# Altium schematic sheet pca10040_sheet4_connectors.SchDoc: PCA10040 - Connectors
size A3; Revision: 1.1.0; SheetNumber: 4; SheetTotal: 5; DrawnBy: KJP; ProjectNumber: 4397; PCAName: PCA10040; PCBRevision: 0071KJP; DocumentSize: A3; PCBNumber: 400150
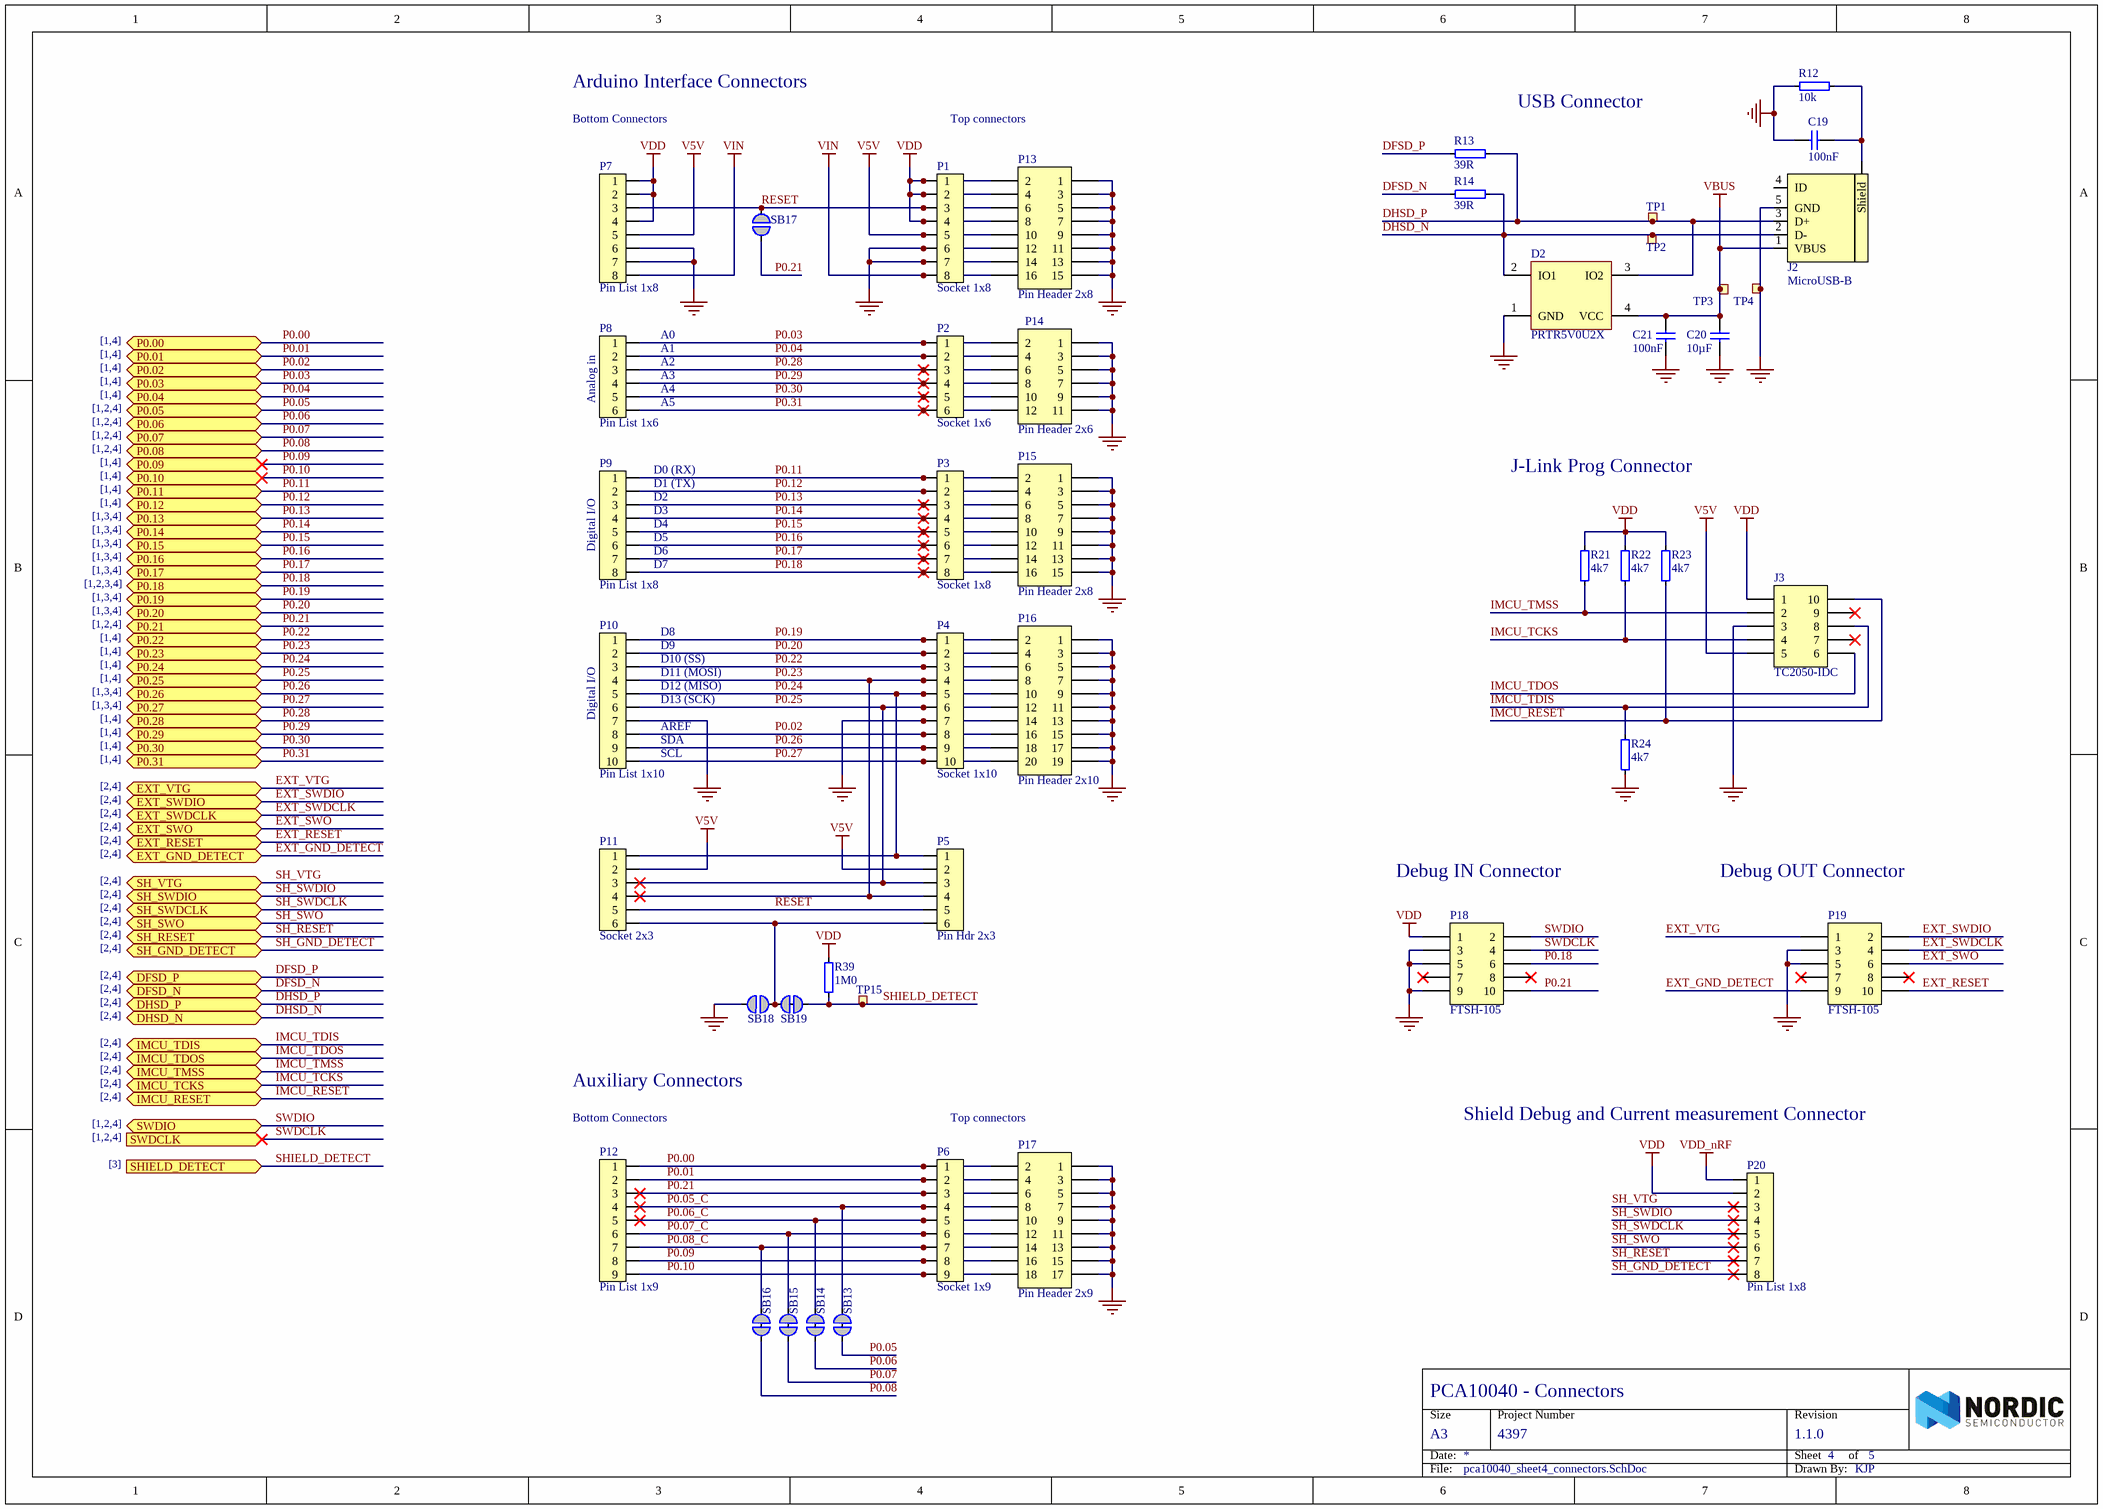
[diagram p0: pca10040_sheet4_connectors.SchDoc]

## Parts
C19  100nF  [CAPC1005X04L]
C20  10µF  [CAPC1608X06L]
C21  100nF  [CAPC1005X04L]
D2  PRTR5V0U2X  [SOT190P230X110-4L]
J2  MicroUSB-B  [FCI_10118193-0001LF]
J3  TC2050-IDC  [TC2050-IDC-NLFP]  (no BOM)
P1  Socket 1x8  [SOCKET_1x8_SMD]
P2  Socket 1x6  [SOCKET_1x6_SMD]
P3  Socket 1x8  [SOCKET_1x8_SMD]
P4  Socket 1x10  [SOCKET_1x10_SMD]
P5  Pin Hdr 2x3  [Molex 15-91-2060]
P6  Socket 1x9  [SOCKET_1x9_SMD]
P7  Pin List 1x8  [LIST_1x8_SMD]
P8  Pin List 1x6  [LIST_1x6_SMD]
P9  Pin List 1x8  [LIST_1x8_SMD]
P10  Pin List 1x10  [LIST_1x10_SMD]
P11  Socket 2x3  [SOCKET_2x3_SMD-2.54mm-bottom]
P12  Pin List 1x9  [LIST_1x9_SMD]
P13  Pin Header 2x8  [HDR_2x8]
P14  Pin Header 2x6  [HDR_2x6]
P15  Pin Header 2x8  [HDR_2x8]
P16  Pin Header 2x10  [HDR_2x10]
P17  Pin Header 2x9  [HDR_2x9]
P18  FTSH-105  [FTSH-105-K]
P19  FTSH-105  [FTSH-105-K]
P20  Pin List 1x8  [LIST_1x8_SMD]
R12  10k  [RESC1005X04L]
R13  39R  [RESC1005X04L]
R14  39R  [RESC1005X04L]
R21  4k7  [RESC1005X04L]
R22  4k7  [RESC1005X04L]
R23  4k7  [RESC1005X04L]
R24  4k7  [RESC1005X04L]
R39  1M0  [RESC1005X04L]
SB13  Solderbridge  [Solderbridge_Shorted]  (value not drawn)  (net tie, no BOM)
SB14  Solderbridge  [Solderbridge_Shorted]  (value not drawn)  (net tie, no BOM)
SB15  Solderbridge  [Solderbridge_Shorted]  (value not drawn)  (net tie, no BOM)
SB16  Solderbridge  [Solderbridge_Shorted]  (value not drawn)  (net tie, no BOM)
SB17  Solderbridge  [Solderbridge]  (value not drawn)  (no BOM)
SB18  Solderbridge  [Solderbridge]  (value not drawn)  (no BOM)
SB19  Solderbridge  [Solderbridge_Shorted]  (value not drawn)  (net tie, no BOM)
TP1  Ø1.0mm,SMD  [TP_SMD_Ø1.0mm]  (value not drawn)  (no BOM)
TP2  Ø1.0mm,SMD  [TP_SMD_Ø1.0mm]  (value not drawn)  (no BOM)
TP3  Ø1.0mm,SMD  [TP_SMD_Ø1.0mm]  (value not drawn)  (no BOM)
TP4  Ø1.0mm,SMD  [TP_SMD_Ø1.0mm]  (value not drawn)  (no BOM)
TP15  Ø1.0mm,SMD  [TP_SMD_Ø1.0mm]  (value not drawn)  (no BOM)

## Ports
DFSD_N (bidir), DFSD_P (bidir), DHSD_N (bidir), DHSD_P (bidir), EXT_GND_DETECT (bidir), EXT_RESET (bidir), EXT_SWDCLK (bidir), EXT_SWDIO (bidir), EXT_SWO (bidir), EXT_VTG (bidir), IMCU_RESET (bidir), IMCU_TCKS (bidir), IMCU_TDIS (bidir), IMCU_TDOS (bidir), IMCU_TMSS (bidir), P0.00 (bidir), P0.01 (bidir), P0.02 (bidir), P0.03 (bidir), P0.04 (bidir), P0.05 (bidir), P0.06 (bidir), P0.07 (bidir), P0.08 (bidir), P0.09 (bidir), P0.10 (bidir), P0.11 (bidir), P0.12 (bidir), P0.13 (bidir), P0.14 (bidir), P0.15 (bidir), P0.16 (bidir), P0.17 (bidir), P0.18 (bidir), P0.19 (bidir), P0.20 (bidir), P0.21 (bidir), P0.22 (bidir), P0.23 (bidir), P0.24 (bidir), P0.25 (bidir), P0.26 (bidir), P0.27 (bidir), P0.28 (bidir), P0.29 (bidir), P0.30 (bidir), P0.31 (bidir), SH_GND_DETECT (bidir), SH_RESET (bidir), SH_SWDCLK (bidir), SH_SWDIO (bidir), SH_SWO (bidir), SH_VTG (bidir), SHIELD_DETECT (in), SWDCLK (in), SWDIO (bidir)

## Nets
GND: C19.1 C20.1 C21.1 D2.1(GND) J2.5(GND) J3.3 P1.6 P1.7 P4.7 P7.6 P7.7 P10.7 P13.1 P13.3 P13.5 P13.7 P13.9 P13.11 P13.12 P13.13 P13.14 P13.15 P14.1 P14.3 P14.5 P14.7 P14.9 P14.11 P15.1 P15.3 P15.5 P15.7 P15.9 P15.11 P15.13 P15.15 P16.1 P16.3 P16.5 P16.7 P16.9 P16.11 P16.13 P16.14 P16.15 P16.17 P16.19 P17.1 P17.3 P17.5 P17.7 P17.9 P17.11 P17.13 P17.15 P17.17 P18.3 P18.5 P18.9 P19.3 P19.5 R12.1 R24.2 SB18.1 TP4.1
V5V: J3.5 P1.5 P5.2 P7.5 P11.2 P13.10
VBUS: C20.2 C21.2 D2.4(VCC) J2.1(VBUS) TP3.1
VDD: J3.1 P1.1 P1.2 P1.4 P7.1 P7.2 P7.4 P13.2 P13.4 P13.8 P18.1 P20.2 R21.2 R22.2 R23.2 R39.2
VDD_nRF: P20.1
VIN: P1.8 P7.8 P13.16
DFSD_N: R14.1 ; port DFSD_N
DFSD_P: R13.1 ; port DFSD_P
DHSD_N: D2.2(IO1) J2.2(D-) R14.2 TP2.1 ; port DHSD_N
DHSD_P: D2.3(IO2) J2.3(D+) R13.2 TP1.1 ; port DHSD_P
EXT_GND_DETECT: P19.9 ; port EXT_GND_DETECT
EXT_RESET: P19.10 ; port EXT_RESET
EXT_SWDCLK: P19.4 ; port EXT_SWDCLK
EXT_SWDIO: P19.2 ; port EXT_SWDIO
EXT_SWO: P19.6 ; port EXT_SWO
EXT_VTG: P19.1 ; port EXT_VTG
IMCU_RESET: J3.10 R23.1 ; port IMCU_RESET
IMCU_TCKS: J3.4 R22.1 ; port IMCU_TCKS
IMCU_TDIS: J3.8 R24.1 ; port IMCU_TDIS
IMCU_TDOS: J3.6 ; port IMCU_TDOS
IMCU_TMSS: J3.2 R21.1 ; port IMCU_TMSS
P0.00: P6.1 P12.1 P17.2 ; port P0.00
P0.01: P6.2 P12.2 P17.4 ; port P0.01
P0.02: P4.8 P10.8 P16.16 ; port P0.02
P0.03: P2.1 P8.1 P14.2 ; port P0.03
P0.04: P2.2 P8.2 P14.4 ; port P0.04
P0.05: SB13.2 ; port P0.05
P0.05_C: P6.4 P12.4 P17.8 SB13.1
P0.06: SB14.2 ; port P0.06
P0.06_C: P6.5 P12.5 P17.10 SB14.1
P0.07: SB15.2 ; port P0.07
P0.07_C: P6.6 P12.6 P17.12 SB15.1
P0.08: SB16.2 ; port P0.08
P0.08_C: P6.7 P12.7 P17.14 SB16.1
P0.09: P6.8 P12.8 P17.16 ; port P0.09
P0.10: P6.9 P12.9 P17.18 ; port P0.10
P0.11: P3.1 P9.1 P15.2 ; port P0.11
P0.12: P3.2 P9.2 P15.4 ; port P0.12
P0.13: P3.3 P9.3 P15.6 ; port P0.13
P0.14: P3.4 P9.4 P15.8 ; port P0.14
P0.15: P3.5 P9.5 P15.10 ; port P0.15
P0.16: P3.6 P9.6 P15.12 ; port P0.16
P0.17: P3.7 P9.7 P15.14 ; port P0.17
P0.18: P3.8 P9.8 P15.16 P18.6 ; port P0.18
P0.19: P4.1 P10.1 P16.2 ; port P0.19
P0.20: P4.2 P10.2 P16.4 ; port P0.20
P0.21: P6.3 P12.3 P17.6 P18.10 SB17.2 ; port P0.21
P0.22: P4.3 P10.3 P16.6 ; port P0.22
P0.23: P4.4 P5.4 P10.4 P11.4 P16.8 ; port P0.23
P0.24: P4.5 P5.1 P10.5 P11.1 P16.10 ; port P0.24
P0.25: P4.6 P5.3 P10.6 P11.3 P16.12 ; port P0.25
P0.26: P4.9 P10.9 P16.18 ; port P0.26
P0.27: P4.10 P10.10 P16.20 ; port P0.27
P0.28: P2.3 P8.3 P14.6 ; port P0.28
P0.29: P2.4 P8.4 P14.8 ; port P0.29
P0.30: P2.5 P8.5 P14.10 ; port P0.30
P0.31: P2.6 P8.6 P14.12 ; port P0.31
RESET: P1.3 P5.5 P7.3 P11.5 P13.6 SB17.1
SH_GND_DETECT: P20.8 ; port SH_GND_DETECT
SH_RESET: P20.7 ; port SH_RESET
SH_SWDCLK: P20.5 ; port SH_SWDCLK
SH_SWDIO: P20.4 ; port SH_SWDIO
SH_SWO: P20.6 ; port SH_SWO
SH_VTG: P20.3 ; port SH_VTG
SHIELD_DETECT: R39.1 SB19.2 TP15.1 ; port SHIELD_DETECT
SWDCLK: P18.4 ; port SWDCLK
SWDIO: P18.2 ; port SWDIO
NetC19_2: C19.2 J2.6(Shield) R12.2
NetP5_6: P5.6 P11.6 SB18.2 SB19.1

Not connected (* = marked no-connect by the designer): J2 4(ID); J3 7* 9*; P18 7* 8*; P19 7* 8*

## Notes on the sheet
- Arduino Interface Connectors
- (near R13) USB Connector
- Bottom Connectors
- Top connectors
- [1,4]
- (near P8) A0
- (near P8) A1
- (near P8) A2
- (near P8) A3
- [1,2,4]
- (near P8) Analog in
- (near P8) A4
- (near P8) A5
- [1,3,4]
- (near P9) D0 (RX)
- (near P9) D1 (TX)
- (near P9) D2
- (near P9) D3
- J-Link Prog Connector
- [1,2,3,4]
- (near P9) Digital I/O
- (near P9) D4
- (near P9) D5
- (near P9) D6
- (near P9) D7
- (near P10) D8
- (near P10) D9
- (near P10) Digital I/O
- (near P10) D10 (SS)
- (near P10) D11 (MOSI)
- (near P10) D12 (MISO)
- (near P10) D13 (SCK)
- [2,4]
- (near P10) AREF
- (near P10) SDA
- (near P10) SCL
- Debug IN Connector
- Debug OUT Connector
- Auxiliary Connectors
- (near P12) Bottom Connectors
- Shield Debug and Current measurement Connector
- [3]

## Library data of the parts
C19 C21 = C0402-100n: Capacitor, X7R, ±10%; Note: 16V; Artikkelnr Noca: 20039200; Artikkelnr Simpro: N.A.
C20 = C0603-10µ: Capacitor, X5R, ±20%; Note: 6.3V; Artikkelnr Noca: 20039234; Artikkelnr Simpro: N.A.
D2 = PRTR5V0U2X: Ultra low capacitance double rail-to-rail ESD protection diode; Manufacturer: NXP; 2nd source part number: 152-4157; Artikkelnr Noca: 10069015; Artikkelnr Simpro: N.A.
J2 = FCI 10118193-0001LF: MicroUSB-B-SMT; Manufacturer: FCI; 2nd source part number: 649-10118193-0001LF; Artikkelnr Noca: N.A.
J3 = TC2050-IDC-NLFP: CBL PLUG-OF-NAILS 10-PIN; Manufacturer: Tag-Connect LLC; Artikkelnr Noca: N.A.
P1 P3 = Socket 1x8 SMD: Socket 1x8, 2.54mm (100mil), SMD; Manufacturer: Cabcon; Manufacturer Part Number: 2171-108MS0CUNR1; 2nd source part number: SSM-108-F-SV-P-TR; Artikkelnr Noca: 55030002; Artikkelnr Simpro: N.A.
P2 = Socket 1x6 SMD: Socket 1x6, 2.54mm (100mil), SMD; Manufacturer: Cabcon; Manufacturer Part Number: 2171-106MS0CUNR1; 2nd source part number: SSM-106-F-SV-P-TR; Artikkelnr Noca: 55030001; Artikkelnr Simpro: N.A.
P4 = Socket 1x10 SMD: Socket 1x10, 2.54mm (100mil), SMD; Manufacturer: Cabcon; Manufacturer Part Number: 2171-110MS0CUNR1; 2nd source part number: SSM-110-F-SV-P-TR; Artikkelnr Noca: 55030004; Artikkelnr Simpro: N.A.
P5 = Pin Header 2x3 SMD: Pin Header 2x3, 2.54mm (100mil) SMD; Manufacturer: Cabcon; Manufacturer Part Number: 1125-1203S3M115R1; 2nd source part number: TSM-103-01-L-DV; Artikkelnr Noca: 55010007; Artikkelnr Simpro: N.A.
P6 = Socket 1x9 SMD: Socket 1x9, 2.54mm (100mil), SMD; Manufacturer: Cabcon; Manufacturer Part Number: 2171-109MS3CUNR1; 2nd source part number: SSM-109-L-SV; Artikkelnr Noca: 55030003; Artikkelnr Simpro: N.A.
P7 P9 = Pin List 1x8 SMD: Pin List 1x8, 2.54mm (100mil), SMD; Note: Not mounted; Artikkelnr Noca: 55019253; Artikkelnr Simpro: N.A.
P8 = Pin List 1x6 SMD: Pin List 1x6, 2.54mm (100mil), SMD; Note: Not mounted; Artikkelnr Noca: 55019252; Artikkelnr Simpro: N.A.
P10 = Pin List 1x10 SMD: Pin List 1x10, 2.54mm (100mil), SMD; Note: Not mounted; Artikkelnr Noca: 55019254; Artikkelnr Simpro: N.A.
P11 = Socket 2x3 SMD Bottom: Socket 2x3, 2.54mm (100mil), SMD; Manufacturer: Samtec; Manufacturer Part Number: SSM-103-F-DV-P-TR; 2nd source part number: S5712-ND; Note: Not mounted; Artikkelnr Noca: 55019255; Artikkelnr Simpro: N.A.
P12 = Pin List 1x9 SMD: Pin List 1x9, 2.54mm (100mil), SMD; Artikkelnr Noca: N.A.
P13 P15 = Pin Header 2x8: Pin Header 2x8, 2.54mm (100mil); Note: Not mounted; Artikkelnr Noca: N.A.
P14 = Pin Header 2x6: Pin Header 2x6, 2.54mm (100mil); Note: Not mounted; Artikkelnr Noca: N.A.
P16 = Pin Header 2x10: Pin Header 2x10, 2.54mm (100mil); Note: Not mounted; Artikkelnr Noca: N.A.
P17 = Pin Header 2x9: Pin Header 2x9, 2.54mm (100mil); Artikkelnr Noca: N.A.
P18 P19 = Samtec FTSH-105 Keying Shroud: CONN HEADER 10POS DUAL .05" SMD KEYING SHROUD; Manufacturer: Cabcon; Manufacturer Part Number: 3132-10MS0BK00R1; 2nd source part number: FTSH-105-01-F-DV-K; Note: HEADER, 1.27MM, SMD, 10WAY, Keying Shroud; Artikkelnr Noca: 55010009; Artikkelnr Simpro: N.A.
P20 = Pin List 1x8 SMD: Pin List 1x8, 2.54mm (100mil), SMD; Manufacturer: Cabcon; Manufacturer Part Number: 1125-1108S3M115R2; 2nd source part number: TSM-108-01-L-SV-P-TR; Artikkelnr Noca: 55010006; Artikkelnr Simpro: N.A.
R12 = R0402-10k: Resistor, ±1%, 0.063W; Note: Chip Res 1%; Artikkelnr Noca: 27049097; Artikkelnr Simpro: N.A.
R13 R14 = R0402-39R: Resistor, ±1%, 0.063W; Note: Chip Res 1%; Artikkelnr Noca: 27049039; Artikkelnr Simpro: N.A.
R21-R24 = R0402-4k7: Resistor, ±1%, 0.063W; Note: Chip Res 1%; Artikkelnr Noca: 27049089; Artikkelnr Simpro: N.A.
R39 = R0402-1M0: Resistor, ±1%, 0.063W; Note: Chip Res 1%; Artikkelnr Noca: 27049145; Artikkelnr Simpro: N.A.
SB13-SB16 SB19 = Solderbridge Shorted: Shorted Solderbridge; Artikkelnr Noca: N.A.
SB17 SB18 = Solderbridge: Artikkelnr Noca: N.A.
TP1-TP4 TP15 = TP_SMD_Ø1.0MM: 1.0mm circular SMD testpad; Manufacturer: Nordic Semiconductor; Artikkelnr Noca: N.A.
